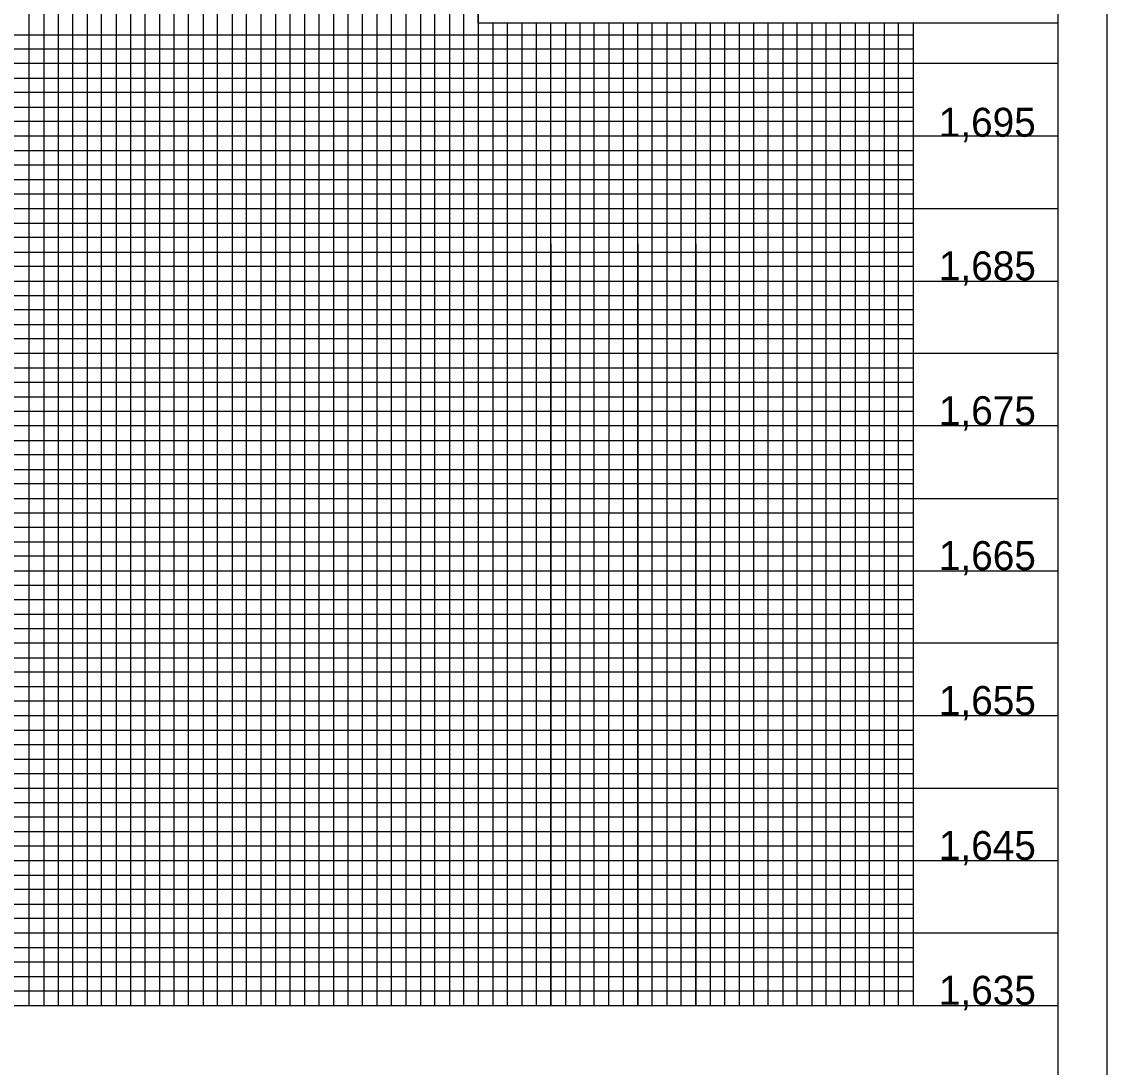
# Model space of a CAD drawing. Extents: x 502400 to 509344, y 448070 to 484209.
# Drawn here: x 506911.5 to 507286.1, y 483662.4 to 484023.2 of the extents above; entities that cross this region are included whole.
import ezdxf

# ---------------------------------------------------------------- set-up
doc = ezdxf.new("R2010")
doc.units = 0
for name, color, linetype in [('Exist Vertical Profile Vertical Axis Label', 7, 'Continuous'), ('Sheet Plot Border Outside CELL', 7, 'Continuous'), ('Sheet Profile CELL', 7, 'Continuous'), ('Sheet Profile Grid Major CELL', 7, 'Continuous'), ('Sheet Profile Grid Middle CELL', 7, 'Continuous'), ('Sheet Profile Grid Minor CELL', 7, 'Continuous'), ('Sheet Sticker Exception Certification CELL', 7, 'Continuous')]:
    doc.layers.add(name, color=color, linetype=linetype)

msp = doc.modelspace()

# ---------------------------------------------------------------- linework, layer by layer
at = {"layer": 'Sheet Plot Border Outside CELL'}
msp.add_lwpolyline([(505602.08, 483108.71), (507286.08, 483108.71), (507286.08, 484208.71), (505602.08, 484208.71)], close=True, dxfattribs=at)
at = {"layer": 'Sheet Profile CELL'}
msp.add_line((505769.08, 483683.71), (507269.08, 483683.71), dxfattribs=at)
msp.add_lwpolyline([(507269.08, 484183.71), (505769.08, 484183.71), (505769.08, 483133.71), (507269.08, 483133.71)], close=True, dxfattribs=at)
at = {"layer": 'Sheet Profile Grid Major CELL'}
for points in [[(506519.08, 483683.71), (506569.08, 483683.71), (506569.08, 484183.71), (506619.08, 484183.71), (506619.08, 483683.71), (506669.08, 483683.71), (506669.08, 484183.71), (506719.08, 484183.71), (506719.08, 483683.71), (506769.08, 483683.71), (506769.08, 484183.71), (506819.08, 484183.71), (506819.08, 483683.71), (506869.08, 483683.71), (506869.08, 484183.71), (506919.08, 484183.71), (506919.08, 483683.71), (506969.08, 483683.71), (506969.08, 484183.71), (507019.08, 484183.71), (507019.08, 483683.71), (507069.08, 483683.71), (507069.08, 484183.71), (507095.38, 484183.71)], [(507219.08, 484022.66), (507219.08, 483683.71), (507269.08, 483683.71), (507269.08, 484033.71)], [(507119.08, 484022.66), (507119.08, 483683.71), (507169.08, 483683.71), (507169.08, 483683.71), (507169.08, 484022.66)], [(507269.08, 483983.71), (505769.08, 483983.71), (505769.08, 483933.71), (507269.08, 483933.71)], [(507269.08, 483883.71), (505769.08, 483883.71), (505769.08, 483833.71), (507269.08, 483833.71)], [(507269.08, 483783.71), (505769.08, 483783.71), (505769.08, 483783.71), (505769.08, 483733.71), (507269.08, 483733.71)]]:
    msp.add_lwpolyline(points, dxfattribs=at)
at = {"layer": 'Sheet Profile Grid Middle CELL'}
for points in [[(506894.08, 484183.71), (506944.08, 484183.71), (506944.08, 483683.71), (506994.08, 483683.71), (506994.08, 484183.71), (507044.08, 484183.71), (507044.08, 483683.71), (507094.08, 483683.71), (507094.08, 484022.66)], [(507094.08, 483946.51), (507094.08, 483683.71), (507144.08, 483683.71), (507144.08, 484022.66)], [(507144.08, 483946.51), (507144.08, 483683.71), (507194.08, 483683.71), (507194.08, 484022.66)], [(507269.08, 484008.71), (505769.08, 484008.71), (505769.08, 483958.71), (507094.08, 483958.71)], [(507094.08, 483958.71), (507269.08, 483958.71)], [(507269.08, 483908.71), (505769.08, 483908.71), (505769.08, 483858.71), (507269.08, 483858.71)], [(507269.08, 483808.71), (505769.08, 483808.71), (505769.08, 483758.71), (507269.08, 483758.71)], [(507269.08, 483708.71), (505769.08, 483708.71)]]:
    msp.add_lwpolyline(points, dxfattribs=at)
at = {"layer": 'Sheet Profile Grid Minor CELL'}
for p, q in [((505819.08, 484018.71), (507219.08, 484018.71)), ((507219.08, 483998.71), (505819.08, 483998.71)), ((505819.08, 483993.71), (507219.08, 483993.71)), ((507219.08, 483973.71), (505819.08, 483973.71)), ((505819.08, 483968.71), (507219.08, 483968.71)), ((507219.08, 483948.71), (505819.08, 483948.71)), ((505819.08, 483943.71), (507219.08, 483943.71)), ((507219.08, 483938.71), (505819.08, 483938.71)), ((505819.08, 483928.71), (507219.08, 483928.71)), ((507219.08, 483923.71), (505819.08, 483923.71)), ((505819.08, 483918.71), (507219.08, 483918.71)), ((507219.08, 483913.71), (505819.08, 483913.71)), ((505819.08, 483903.71), (507219.08, 483903.71)), ((507219.08, 483898.71), (505819.08, 483898.71)), ((505819.08, 483893.71), (507219.08, 483893.71)), ((507219.08, 483888.71), (505819.08, 483888.71)), ((505819.08, 483878.71), (507219.08, 483878.71)), ((507219.08, 483873.71), (505819.08, 483873.71)), ((505819.08, 483868.71), (507219.08, 483868.71)), ((507219.08, 483863.71), (505819.08, 483863.71)), ((505819.08, 483853.71), (507219.08, 483853.71)), ((507219.08, 483848.71), (505819.08, 483848.71)), ((505819.08, 483843.71), (507219.08, 483843.71)), ((507219.08, 483838.71), (505819.08, 483838.71)), ((505819.08, 483828.71), (507219.08, 483828.71)), ((507219.08, 483823.71), (505819.08, 483823.71)), ((505819.08, 483818.71), (507219.08, 483818.71)), ((507219.08, 483813.71), (505819.08, 483813.71)), ((505819.08, 483803.71), (507219.08, 483803.71)), ((507219.08, 483798.71), (505819.08, 483798.71)), ((507219.08, 483793.71), (505819.08, 483793.71)), ((507219.08, 483788.71), (505819.08, 483788.71)), ((505819.08, 483778.71), (507219.08, 483778.71)), ((507219.08, 483773.71), (505819.08, 483773.71)), ((505819.08, 483768.71), (507219.08, 483768.71)), ((507219.08, 483763.71), (505819.08, 483763.71)), ((505819.08, 483753.71), (507219.08, 483753.71)), ((507219.08, 483748.71), (505819.08, 483748.71)), ((505819.08, 483743.71), (507219.08, 483743.71)), ((507219.08, 483738.71), (505819.08, 483738.71)), ((505819.08, 483728.71), (507219.08, 483728.71)), ((507219.08, 483723.71), (505819.08, 483723.71)), ((505819.08, 483718.71), (507219.08, 483718.71)), ((507219.08, 483713.71), (505819.08, 483713.71)), ((505819.08, 483703.71), (507219.08, 483703.71)), ((507219.08, 483698.71), (505819.08, 483698.71)), ((505819.08, 483693.71), (507219.08, 483693.71))]:
    msp.add_line(p, q, dxfattribs=at)
for points in [[(506909.08, 483683.71), (506914.08, 483683.71), (506914.08, 484183.71), (506924.08, 484183.71), (506924.08, 483683.71), (506929.08, 483683.71), (506929.08, 484183.71), (506934.08, 484183.71), (506934.08, 483683.71), (506939.08, 483683.71), (506939.08, 484183.71), (506949.08, 484183.71), (506949.08, 483683.71), (506954.08, 483683.71), (506954.08, 484183.71), (506959.08, 484183.71), (506959.08, 483683.71)], [(506959.08, 483683.71), (506964.08, 483683.71), (506964.08, 484183.71)], [(506974.08, 484183.71), (506974.08, 483683.71), (506979.08, 483683.71), (506979.08, 484183.71)], [(506984.08, 484183.71), (506984.08, 483683.71), (506989.08, 483683.71), (506989.08, 484183.71)], [(506999.08, 484183.71), (506999.08, 483683.71), (507004.08, 483683.71), (507004.08, 484183.71)], [(507009.08, 484183.71), (507009.08, 483683.71), (507014.08, 483683.71), (507014.08, 484183.71)], [(507024.08, 484183.71), (507024.08, 483683.71), (507029.08, 483683.71), (507029.08, 484183.71)], [(507034.08, 484183.71), (507034.08, 483683.71), (507039.08, 483683.71), (507039.08, 484183.71)], [(507049.08, 484183.71), (507049.08, 483683.71), (507054.08, 483683.71), (507054.08, 484183.71)], [(507059.08, 484183.71), (507059.08, 483683.71), (507064.08, 483683.71), (507064.08, 484183.71)], [(507074.08, 484022.66), (507074.08, 483683.71), (507079.08, 483683.71), (507079.08, 484022.66)], [(507084.08, 484022.66), (507084.08, 483683.71), (507089.08, 483683.71), (507089.08, 484022.66)], [(507099.08, 484022.66), (507099.08, 483683.71), (507099.08, 483683.71), (507104.08, 483683.71), (507109.08, 483683.71), (507109.08, 484022.66)], [(507104.08, 484022.66), (507104.08, 483683.71)], [(507114.07, 484022.66), (507113.98, 483683.76), (507118.98, 483683.76), (507124.08, 483683.71), (507124.08, 484022.66)], [(507124.08, 483946.51), (507124.08, 483683.71), (507129.08, 483683.71), (507129.08, 484022.66)], [(507134.08, 484022.66), (507134.08, 483683.71), (507139.08, 483683.71), (507139.08, 484022.66)], [(507149.08, 484022.66), (507149.08, 483683.71), (507154.08, 483683.71), (507154.08, 484022.66)], [(507159.08, 484022.66), (507159.08, 483683.71), (507164.08, 483683.71), (507164.08, 484022.66)], [(507174.08, 484022.66), (507174.08, 483683.71), (507179.08, 483683.71), (507179.08, 484022.66)], [(507184.08, 484022.66), (507184.08, 483683.71), (507189.08, 483683.71), (507189.08, 484022.66)], [(507199.08, 484022.66), (507199.08, 483683.71), (507204.08, 483683.71), (507204.08, 484022.66)], [(507209.08, 484022.66), (507209.08, 483683.71), (507214.08, 483683.71), (507214.08, 484022.66)], [(507219.08, 484013.71), (505819.08, 484013.71), (505819.08, 484003.71), (507219.08, 484003.71)], [(507219.08, 483988.71), (505819.08, 483988.71), (505819.08, 483978.71), (507219.08, 483978.71)], [(507219.08, 483963.71), (505819.08, 483963.71), (505819.08, 483953.71), (507219.08, 483953.71)], [(507219.08, 483688.71), (505819.08, 483688.71)]]:
    msp.add_lwpolyline(points, dxfattribs=at)
at = {"layer": 'Sheet Sticker Exception Certification CELL'}
for p, q in [((507069.03, 484022.66), (507069.03, 484046.16)), ((507069.03, 484022.66), (507069.03, 484046.16)), ((507269.07, 484046.15), (507269.07, 484022.65)), ((507269.07, 484046.15), (507269.07, 484022.65)), ((507269.07, 484022.66), (507069.03, 484022.66)), ((507269.07, 484022.66), (507069.03, 484022.66))]:
    msp.add_line(p, q, dxfattribs=at)

# ---------------------------------------------------------------- texts
at = {"layer": 'Exist Vertical Profile Vertical Axis Label'}
for s, p in [('1,695', (507227.93, 483983.48)), ('1,685', (507227.97, 483933.96)), ('1,675', (507227.97, 483883.96)), ('1,665', (507227.97, 483833.96)), ('1,655', (507227.97, 483783.96)), ('1,645', (507227.97, 483733.96)), ('1,635', (507227.97, 483683.96))]:
    msp.add_text(s, height=10, dxfattribs=at).set_placement(p)

doc.saveas('drawing.dxf')
